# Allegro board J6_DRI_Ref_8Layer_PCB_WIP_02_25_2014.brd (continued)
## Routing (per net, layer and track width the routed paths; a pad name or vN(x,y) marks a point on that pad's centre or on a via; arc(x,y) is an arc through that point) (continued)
H_DDR1_D29: length 36.6
  TOP w0.102: U52.AA26 v1(61.35,49.34)
  TOP w0.127: v1(42.18,31.3) U66.C2
  BOTTOM w0.127: v1(42.18,31.3) 41.78,31.7 41.78,32.39 41.99,32.59 41.99,32.8 42.09,32.9 42.32,32.9 42.42,33 42.42,33.21 42.32,33.31 42.09,33.31 41.99,33.41 41.99,33.7 41.88,33.81 41.37,33.81 41.25,33.93 41.25,34.09 41.37,34.21 41.88,34.21 41.99,34.31 41.99,34.67 42.09,34.77 42.3,34.77 42.42,34.89 42.42,35.06 42.3,35.18 42.09,35.18 41.99,35.28 41.99,35.64 42.89,36.54 43.03,36.54 43.2,36.37 43.35,36.37 43.49,36.51 43.49,36.65 43.32,36.83 43.32,36.97 43.46,37.11 43.61,37.11 43.78,36.94 43.92,36.94 44.07,37.09 44.07,37.23 43.89,37.4 43.89,37.55 44.04,37.69 44.18,37.69 44.36,37.52 44.5,37.52 44.64,37.66 44.64,37.8 44.47,37.98 44.47,38.12 45.42,39.07 46.56,39.07 46.69,38.94 46.69,38.69 46.81,38.56 47.14,38.56 47.27,38.69 47.27,38.94 47.4,39.07 48.18,39.07 48.31,39.19 48.31,39.42 48.44,39.55 49.91,39.55 51.41,41.05 51.41,41.28 51.81,41.68 51.86,41.68 53.29,43.11 53.29,43.45 53.58,43.73 54.09,43.73 55.45,45.09 55.8,45.09 55.96,44.94 56.79,44.94 58.09,46.23 58.37,46.23 60.95,48.81 v1(61.35,49.34)
H_DDR1_D30: length 30.6
  TOP w0.102: U52.AA25 61.79,50.31 v1(61.38,49.95)
  TOP w0.127: v1(42.98,32.9) U66.A2
  BOTTOM w0.102: v1(61.38,49.95) 61.74,49.59 61.74,49.09 61.6,48.96 61.6,48.75
  BOTTOM w0.127: 61.6,48.75 59.01,46.15 58.91,46.15 58.17,45.42 57.79,45.42 57.51,45.13 57.51,44.55 56.31,43.36 55.8,43.36 51.51,39.07 50.79,39.07 50.05,38.33 48.39,38.33 47.92,37.86 46.11,37.86 45.41,37.16 44.91,37.16 43.56,35.81 43.17,35.81 42.98,35.63 42.98,34.19 42.88,34.09 42.61,34.09 42.49,33.97 42.49,33.8 42.61,33.68 42.88,33.68 42.98,33.58 v1(42.98,32.9)
H_DDR1_D31: length 32
  TOP w0.127: U52.AA28 61.93,47.28 61.06,46.41 61.06,43.46 60.68,43.08 60.68,40.24 59,38.56 57.84,38.56 57.37,38.09 57.37,37.71 56.63,36.97 55.9,36.97 55.45,36.52 55.45,35.49 55.19,35.23 46.59,35.23 45.75,34.39 45.75,31.5 45.85,31.4 46.08,31.4 46.18,31.3 46.18,31.1 46.08,30.99 45.85,30.99 45.75,30.89 45.75,30.48 46.13,30.09 U66.D7
H_DDR1_DQM0: length 43.4
  TOP w0.102: v1(59.13,51.63) U52.AD23
  TOP w0.127: U65.E7 v1(34.28,29.7)
  L3-SIGNAL w0.102: 58.75,48.9 58.75,49.39
  L3-SIGNAL w0.114: 58.75,49.39 58.75,49.66 59.54,50.45 59.54,51.22 v1(59.13,51.63) ; 58.75,48.9 58.57,48.72 57.99,48.72 56.9,47.63 54.89,47.63 54.66,47.86 53.92,47.86 52.73,46.66 52.73,44.07 50.5,41.84 49.91,41.84 49.4,41.33 48.26,41.33 47.74,40.81 47.54,40.81 46.81,40.08 46.81,39.88 45.42,38.48 44.96,38.48 44.53,38.05 39.95,38.05 38.18,36.28 38.18,36.13 38.61,35.7 38.61,35.54 38.49,35.42 38.32,35.42 37.89,35.85 37.75,35.85 37.59,35.68 37.59,35.54 38,35.12 38,34.96 37.88,34.84 37.71,34.84 37.3,35.25 37.16,35.25 36.86,34.95 36.86,31.52 36.27,30.94 35.53,30.94 v1(34.28,29.7)
H_DDR1_DQM1: length 48.1
  TOP w0.102: U65.D3 31.18,30.09 v1(31.52,30.43) ; 61.13,52.05 v1(61.57,51.65)
  BOTTOM w0.127: v1(31.52,30.43) 32.59,31.5 32.59,33.58 32.87,33.86 33.11,33.86 33.21,33.96 33.21,34.12 33.33,34.24 33.5,34.24 33.62,34.12 33.62,33.96 33.72,33.86 33.93,33.86 34.03,33.96 34.03,34.12 34.15,34.24 34.31,34.24 34.43,34.12 34.43,33.96 34.54,33.86 34.74,33.86 34.84,33.96 34.84,34.12 34.96,34.24 35.13,34.24 35.25,34.12 35.25,33.96 35.35,33.86 35.55,33.86 35.65,33.96 35.65,34.27 35.75,34.37 35.96,34.37 36.06,34.27 36.06,33.96 36.16,33.86 36.36,33.86 36.47,33.96 36.47,34.27 36.57,34.37 36.77,34.37 36.87,34.27 36.87,33.96 36.97,33.86 37.18,33.86 37.28,33.96 37.28,34.27 37.38,34.37 37.58,34.37 37.68,34.27 37.68,33.96 37.79,33.86 37.99,33.86 38.09,33.96 38.09,34.27 38.19,34.37 38.4,34.37 38.5,34.27 38.5,33.96 38.6,33.86 38.84,33.86 46.69,41.71 46.69,42.17 48.79,44.27 50.39,44.27 50.72,44.6 50.72,45.06 52.86,47.2 53.06,47.2 53.64,47.78 54.88,47.78 55.31,47.35 57.1,47.35 57.68,47.93 58.98,47.93 59.94,48.9 59.94,49.71 60.3,50.07 60.3,50.95 60.58,51.23 61.15,51.23 v1(61.57,51.65)
H_DDR1_DQM2: length 38.3
  TOP w0.102: v1(49.05,28.91) 49.03,28.89 ; v1(60.79,49.26) U52.AC26
  TOP w0.127: U66.E7 46.98,28.89 49.03,28.89
  L3-SIGNAL w0.114: v1(49.05,28.91) 49.05,29.51 49.15,29.62 49.38,29.62 49.48,29.72 49.48,29.92 49.38,30.02 49.15,30.02 49.05,30.12 49.05,30.33 49.15,30.43 49.38,30.43 49.48,30.53 49.48,30.73 49.38,30.83 49.15,30.83 49.05,30.94 49.05,31.14 49.15,31.24 49.38,31.24 49.48,31.34 49.48,31.55 49.38,31.65 49.15,31.65 49.05,31.75 49.05,31.95 49.15,32.05 49.38,32.05 49.48,32.16 49.48,32.36 49.38,32.46 49.15,32.46 49.05,32.56 49.05,32.76 49.15,32.87 49.38,32.87 49.48,32.97 49.48,33.17 49.38,33.27 49.15,33.27 49.05,33.37 49.05,33.58 49.15,33.68 49.38,33.68 49.48,33.78 49.48,33.98 49.38,34.09 49.15,34.09 49.05,34.19 49.05,34.39 49.15,34.49 49.38,34.49 49.48,34.59 49.48,34.8 49.38,34.9 49.15,34.9 49.05,35 49.05,35.64 49.44,36.03 49.58,36.03 49.78,35.83 49.92,35.83 50.07,35.97 50.07,36.11 49.87,36.31 49.87,36.46 50.01,36.6 50.15,36.6 50.35,36.4 50.5,36.4 50.64,36.55 50.64,36.69 50.44,36.89 50.44,37.03 50.59,37.18 50.73,37.18 50.93,36.98 51.07,36.98 51.22,37.12 51.22,37.27 51.02,37.46 51.02,37.61 51.16,37.75 51.3,37.75 51.5,37.55 51.65,37.55 51.79,37.7 51.79,37.84 51.59,38.04 51.59,38.18 51.74,38.33 51.88,38.33 52.08,38.13 52.22,38.13 52.37,38.27 52.37,38.42 52.17,38.61 52.17,38.76 52.31,38.9 52.45,38.9 52.65,38.7 52.8,38.7 52.94,38.85 52.94,38.99 52.74,39.19 52.74,39.33 52.89,39.48 53.03,39.48 53.23,39.28 53.37,39.28 53.52,39.42 53.52,39.57 53.32,39.76 53.32,39.91 56.54,43.13 57.12,43.13 57.38,43.39 57.38,43.97 58.7,45.29 58.7,46.31 60.73,48.34 60.73,48.59 60.79,48.65 v1(60.79,49.26)
H_DDR1_DQM3: length 43.3
  TOP w0.127: U52.AA27 61.49,48.41 61.49,47.25 60.78,46.54 60.78,43.64 60.33,43.18 60.33,40.62 59.79,40.08 58.27,40.08 56.05,37.86 55.49,37.86 54.94,37.32 54.94,35.94 54.83,35.82 54.64,35.82 54.51,35.94 54.51,36.35 54.38,36.48 54.21,36.48 54.08,36.35 54.08,35.63 53.96,35.51 53.79,35.51 53.67,35.63 53.67,35.77 53.55,35.89 53.37,35.89 53.24,35.77 53.24,35.61 53.14,35.51 52.94,35.51 52.84,35.61 52.84,35.77 52.72,35.89 52.55,35.89 52.43,35.77 52.43,35.61 52.33,35.51 52.13,35.51 52.02,35.61 52.02,35.77 51.9,35.89 51.74,35.89 51.62,35.77 51.62,35.61 51.52,35.51 51.31,35.51 51.21,35.61 51.21,35.92 51.11,36.02 47.42,36.02 47.17,36.27 v2(46.76,36.27) ; v1(43.78,30.49) U66.D3
  BOTTOM w0.127: v2(46.76,36.27) 45.92,36.27 45.8,36.15 45.8,35.89 45.92,35.77 46.37,35.77 46.46,35.68 46.46,34.83 46.23,34.59 46.08,34.59 45.44,35.24 45.27,35.24 45.15,35.12 45.15,34.95 45.79,34.31 45.79,34.16 45.65,34.02 45.51,34.02 44.8,34.73 44.63,34.73 44.51,34.61 44.51,34.44 45.22,33.73 45.22,33.59 45.08,33.44 44.93,33.44 44.57,33.81 44.43,33.81 44.28,33.66 44.28,33.52 44.64,33.16 44.64,33.01 43.21,31.57 43.21,31.07 v1(43.78,30.49)
H_DDR1_DQM_ECC: length 29.4
  TOP w0.102: v1(63.75,49.34) U52.V26
  TOP w0.127: v1(59.05,30.27) U67.B7
  L3-SIGNAL w0.102: 62.56,47.17 62.18,46.79
  L3-SIGNAL w0.114: 62.56,47.17 62.56,47.35 63.75,48.54 v1(63.75,49.34) ; 62.18,46.79 61.8,46.41 61.8,40.85 60.91,39.96 60.91,39.61 60.81,39.5 60.3,39.5 60.2,39.4 60.2,39.2 60.3,39.1 60.81,39.1 60.91,39 60.91,38.79 60.81,38.69 60.3,38.69 60.2,38.59 60.2,38.39 60.3,38.28 60.81,38.28 60.91,38.18 60.91,37.98 60.81,37.88 60.3,37.88 60.2,37.78 60.2,37.57 60.3,37.47 60.81,37.47 60.91,37.37 60.91,37.17 60.81,37.07 60.3,37.07 60.2,36.96 60.2,36.76 60.3,36.66 60.83,36.66 60.91,36.58 60.91,36.35 60.81,36.25 60.3,36.25 60.2,36.15 60.2,35.95 60.3,35.85 60.81,35.85 60.91,35.74 60.91,35.51 60.78,35.38 60.4,35.38 60.31,35.3 60.31,33.28 60.44,33.15 60.66,33.15 60.78,33.02 60.78,32.64 60.66,32.51 59.86,32.51 59.05,31.7 v1(59.05,30.27)
H_DDR1_DQS0: length 41.8
  TOP w0.089: 53.8,50.06 53.78,50.06 53.77,50.05 50.87,50.05 49.96,49.14 49.96,48.59 49.38,48.01 48.84,48.01 47.84,47.01 47.84,46.45 48.41,45.88 48.41,45.59 47.75,44.94 47.07,44.94 46.81,44.68 46.81,42.98 41.9,38.07 40.46,38.07 38.67,36.28 34.68,36.28 32.12,33.72 32.12,31.06 32.45,30.73 32.45,30.19 32.02,29.75 32.02,28.98 31.85,28.82 31.73,28.82 31.58,28.97 31.45,28.97 31.33,28.84 31.33,28.71 31.47,28.57 31.47,28.44 31.09,28.06 30.81,28.06 30.68,28.18 U65.F3
  TOP w0.102: U52.AH25 56.2,50.32 55.41,50.32 55.15,50.06 53.8,50.06
H_DDR1_DQS1: length 54.5
  TOP w0.089: U52.AE27 58.73,48.6 58.35,48.17 58.35,47.86 58.39,47.82 ; U65.C7 33.81,30.97 33.38,30.97 32.96,31.38 32.96,33.21 34.35,34.6 35.77,34.6 36.01,34.36 36.01,33.05 36.14,32.92 36.51,32.92 36.64,33.05 36.64,34.36 36.88,34.6 37.48,34.6 37.72,34.36 37.72,29.8 37.85,29.67 38.22,29.67 38.35,29.8 38.35,34.36 38.59,34.6 40.16,34.6 40.35,34.79 40.35,35.31 39.97,35.69 39.97,36.09 40.66,36.78 41.07,36.78 41.41,36.43 41.56,36.43 47.3,42.17 47.88,42.17 48.07,42.35 48.07,42.59 47.86,42.79 47.86,43.55 47.86,43.9 48.56,44.59 49.08,44.59 49.28,44.39 49.72,44.39 49.92,44.59 50.68,44.59 51.13,44.15 52.31,44.15 52.46,43.99 52.64,43.81 52.64,43.27 52.8,43.11 53.05,43.11 53.75,43.81 54,43.81 54.3,44.11 55.51,44.11 55.96,43.67 56.95,43.67 58.31,45.02 58.31,46.67 58.3,46.68 58.3,46.77 58.29,46.77 58.29,46.79
  TOP w0.102: 58.39,47.82 58.45,47.76 58.45,47.55 58.29,47.39 58.29,46.79
H_DDR1_DQS2: length 44.4
  TOP w0.089: U52.AD27 59.53,48.59 59.13,48.08 59.13,47.88 59.19,47.82 ; U66.F3 44.19,28.49 44.35,28.65 44.35,31.5 44.02,31.83 44.02,32.39 44.35,32.72 44.35,33.46 44.2,33.61 41.63,33.61 41.31,33.93 41.31,35.01 42.2,35.9 42.28,35.98 42.75,35.98 43.19,35.54 43.34,35.54 43.63,35.83 43.63,35.98 43.13,36.49 43.13,36.82 43.56,37.25 43.9,37.25 44.4,36.75 44.55,36.75 44.84,37.04 44.84,37.19 44.34,37.7 44.34,37.81 44.34,37.81 44.34,38.03 45.85,39.55 48.33,39.55 48.77,39.98 49.53,39.98 49.79,39.73 50.3,39.73 50.7,40.13 50.7,40.57 50.97,40.83 51.15,40.83 51.49,41.17 51.49,41.88 51.81,42.2 52.33,42.2 52.63,41.91 52.63,41.6 52.63,40.16 52.76,40.03 53.19,40.03 53.31,40.16 53.31,41.54 53.61,41.83 55.37,41.83 56.67,43.13 57.38,43.13 58.99,44.74 58.99,46.67 58.99,46.68 58.99,46.77 58.98,46.77 58.98,46.79
  TOP w0.102: 59.19,47.82 59.25,47.76 59.25,47.55 58.98,47.28 58.98,46.79
H_DDR1_DQS3: length 48.4
  TOP w0.089: U66.C7 47.02,31.33 47.02,33.46 46.62,33.85 46.62,34.1 46.85,34.33 48.07,34.33 48.18,34.23 48.18,33.7 48.44,33.44 49.08,33.44 49.34,33.7 49.34,34.1 49.45,34.21 49.79,34.21 49.89,34.1 49.89,32.61 50.18,32.32 50.77,32.32 51.05,32.61 51.05,34.1 51.16,34.21 51.5,34.21 51.6,34.1 51.6,31.21 51.89,30.93 52.48,30.93 52.76,31.21 ; 52.76,31.57 52.76,34.1 52.87,34.21 53.27,34.21 53.38,34.1 53.38,32.47 53.66,32.18 54.26,32.18 54.54,32.47 54.54,34.04 54.7,34.21 55.59,34.21 56.05,34.66 56.53,34.66 57.5,35.64 57.5,36.2 57.63,36.32 58.09,36.32 58.73,35.69 59.42,35.69 59.69,35.96 59.69,36.4 59.4,36.69 59.4,37.38 59.5,37.49 59.74,37.49 59.87,37.36 59.87,37.15 60.15,36.87 60.7,36.87 60.99,37.15 60.99,37.71 60.41,38.28 60.41,38.76 61.99,40.33 61.99,43.5 61.81,43.67 61.81,46.25 62.08,46.52 62.08,46.52 62.34,46.78 62.35,46.78 62.36,46.79 ; 62.62,47.69 62.73,47.8 U52.Y28
  TOP w0.102: 62.36,46.79 62.62,47.05 62.62,47.69 ; 52.76,31.57 52.76,31.21
H_DDR1_DQS_ECC: length 38.3
  TOP w0.089: U67.C3 56.37,29.06 56.46,29.16 56.46,30.19 56.7,30.43 57.53,30.43 57.63,30.54 57.63,30.95 57.53,31.06 56,31.06 55.71,31.34 ; U52.V27 64.33,48.62 63.94,48.13 ; 55.71,31.57 55.71,31.86 56,32.15 57.53,32.15 57.63,32.25 57.63,32.67 57.53,32.77 56.7,32.77 56.46,33.01 56.46,33.63 57.33,34.5 58.61,34.5 59.11,34 59.11,32.62 59.29,32.44 60.96,32.44 61.76,33.24 61.76,33.52 61.21,34.08 60.84,34.08 60.15,34.77 60.15,35.77 60.54,36.16 62.26,36.16 62.73,36.62 62.73,38.09 63.21,38.57 63.9,38.57 64.15,38.83 64.15,46.42 63.93,46.64 63.93,46.79
  TOP w0.102: 55.71,31.34 55.71,31.57 ; 63.94,48.13 63.94,47.66 63.93,47.66 63.93,46.79
H_DDR1_DQSN0: length 41.8
  TOP w0.089: 53.8,49.78 53.78,49.78 53.77,49.79 50.99,49.79 50.23,49.03 50.23,48.48 49.49,47.74 48.95,47.74 48.11,46.9 48.11,46.56 48.67,45.99 48.67,45.48 47.86,44.67 47.18,44.67 47.08,44.57 47.08,42.87 42.01,37.8 40.57,37.8 38.78,36.02 34.79,36.02 32.39,33.61 32.39,31.17 32.72,30.84 32.72,30.08 32.28,29.64 32.28,28.87 31.2,27.79 30.78,27.79 U65.G3 ; U52.AG25 56.8,50.45
  TOP w0.102: 56.8,50.45 56.66,50.32 56.66,50.32 56.39,50.04 55.53,50.04 55.27,49.78 53.8,49.78
H_DDR1_DQSN1: length 54.4
  TOP w0.089: 58.57,46.79 58.57,44.91 57.06,43.4 55.85,43.4 55.4,43.84 54.41,43.84 54.11,43.54 53.86,43.54 53.16,42.84 52.69,42.84 52.37,43.16 52.37,43.7 52.2,43.88 51.02,43.88 50.57,44.33 50.03,44.33 49.83,44.13 49.17,44.13 48.97,44.33 48.67,44.33 48.13,43.79 48.13,42.9 48.34,42.7 48.34,42.44 48.34,42.44 48.34,42.24 47.99,41.9 47.77,41.9 47.77,41.9 47.41,41.9 41.67,36.16 41.45,36.16 41.45,36.16 41.3,36.16 40.95,36.51 40.78,36.51 40.24,35.98 40.24,35.8 40.62,35.42 40.62,34.68 40.27,34.33 38.7,34.33 38.62,34.25 38.62,29.69 38.33,29.4 37.74,29.4 37.46,29.69 37.46,34.25 37.37,34.33 36.99,34.33 36.9,34.25 36.9,32.94 36.62,32.65 36.03,32.65 35.75,32.94 35.75,34.25 35.66,34.33 34.46,34.33 34.2,34.07 34.2,33.95 34.48,33.66 34.48,33.52 34.37,33.41 34.23,33.41 33.94,33.69 33.82,33.69 33.23,33.1 33.23,31.49 33.49,31.23 33.77,31.23 33.88,31.35 U65.B7
  TOP w0.102: 58.57,46.79 58.57,47.27 58.73,47.43 U52.AE28
H_DDR1_DQSN2: length 44.3
  TOP w0.089: U66.G3 43.38,28.04 43.57,28.23 44.3,28.23 44.61,28.54 44.61,31.61 44.28,31.94 44.28,32.28 44.46,32.45 44.61,32.61 44.61,33.57 44.31,33.87 41.74,33.87 41.57,34.04 41.57,34.9 42.2,35.53 42.39,35.71 42.64,35.71 43.08,35.27 43.45,35.27 43.9,35.72 43.9,36.09 43.39,36.6 43.39,36.71 43.67,36.99 43.78,36.99 44.29,36.48 44.66,36.48 45.11,36.93 45.11,37.3 44.6,37.81 44.6,37.81 44.6,37.92 45.96,39.28 48.44,39.28 48.88,39.72 49.42,39.72 49.68,39.46 50.41,39.46 50.97,40.02 50.97,40.46 51.08,40.57 51.26,40.57 51.75,41.06 51.75,41.77 51.92,41.94 52.22,41.94 52.36,41.8 52.36,40.05 52.52,39.89 52.65,39.77 53.3,39.77 53.58,40.05 53.58,41.43 53.71,41.56 55.47,41.56 56.78,42.87 57.49,42.87 59.26,44.63 59.26,46.79
  TOP w0.102: U52.AD28 59.53,47.44 59.26,47.16 59.26,46.79
H_DDR1_DQSN3: length 48.4
  TOP w0.089: 62.35,48.16 62.73,48.53 U52.Y27 ; 52.6,34.32 52.65,34.37 52.76,34.47 53.38,34.47 53.65,34.21 53.65,32.58 53.77,32.45 54.15,32.45 54.27,32.58 54.27,34.15 54.59,34.47 55.48,34.47 55.93,34.93 56.42,34.93 57.24,35.75 57.24,36.31 57.52,36.59 58.2,36.59 58.84,35.96 59.3,35.96 59.42,36.07 59.42,36.29 59.13,36.58 59.13,37.49 59.39,37.75 59.85,37.75 60.13,37.47 60.13,37.26 60.26,37.14 60.59,37.14 60.72,37.26 60.72,37.6 60.15,38.17 60.15,38.87 61.72,40.44 61.72,43.39 61.54,43.56 61.54,46.36 61.92,46.73 62.09,46.9 62.15,46.97 62.15,46.98 62.16,46.99 ; 62.35,47.81 62.35,47.8 62.35,47.71 62.34,47.71 62.34,47.69 ; U66.B7 46.18,32.09 46.18,33.46 46.36,33.63 46.36,34.21 46.74,34.6 48.19,34.6 48.45,34.34 48.45,33.81 48.55,33.71 48.97,33.71 49.07,33.81 49.07,34.21 49.33,34.47 49.9,34.47 50.16,34.21 50.16,32.72 50.29,32.59 50.66,32.59 50.78,32.72 50.78,34.21 51.05,34.47 51.61,34.47 51.72,34.37 51.87,34.21 51.87,31.32 52,31.19 52.37,31.19 52.5,31.32 52.5,34.21
  TOP w0.102: 62.34,47.69 62.34,47.16 62.16,46.99 ; 62.35,48.16 62.35,47.81 ; 52.6,34.32 52.5,34.21
H_DDR1_DQSN_ECC: length 38.3
  TOP w0.089: U52.V28 64.33,47.79 64.2,47.66 ; 64.21,46.79 64.21,46.77 64.2,46.75 64.42,46.53 64.42,38.72 64.01,38.31 63.32,38.31 62.99,37.98 62.99,36.51 62.37,35.89 60.65,35.89 60.41,35.66 60.41,34.88 60.95,34.34 61.32,34.34 62.03,33.63 62.03,33.13 61.07,32.17 59.18,32.17 58.84,32.51 58.84,33.89 58.5,34.23 57.44,34.23 56.73,33.52 56.73,33.12 56.81,33.04 57.64,33.04 57.9,32.78 57.9,32.14 57.64,31.88 56.11,31.88 55.98,31.75 55.98,31.57 ; 55.98,31.45 56.11,31.32 57.64,31.32 57.9,31.06 57.9,30.43 57.64,30.17 56.81,30.17 56.73,30.08 56.73,29.05 56.48,28.79 55.64,28.79 55.45,28.61 U67.D3
  TOP w0.102: 64.21,46.79 64.21,47.66 64.2,47.66 ; 55.98,31.45 55.98,31.57
H_DDR1_ECC_D0: length 29.7
  TOP w0.102: v1(63.94,53.25) U52.W22
  TOP w0.127: v1(59.05,27.87) U67.E8
  L3-SIGNAL w0.102: 64.21,46.79 64.21,47.95 ; 64.31,51.72 64.31,52.89
  L3-SIGNAL w0.114: 64.21,47.95 64.6,48.34 64.6,51.42 64.31,51.72 ; 64.21,46.79 64.21,46.46 63.76,46.01 63.76,40.85 62.59,39.68 62.59,33.05 61.11,31.57 60.45,31.57 60.25,31.37 60.25,29.27 60.04,29.06 59.66,29.06 59.46,28.86 59.46,28.28 v1(59.05,27.87) ; 64.31,52.89 v1(63.94,53.25)
H_DDR1_ECC_D1: length 27.5
  TOP w0.102: v1(63.93,52.41) U52.V23
  TOP w0.127: v1(59.85,29.47) U67.C8
  L3-SIGNAL w0.102: 63.53,51.46 63.53,52.01
  L3-SIGNAL w0.114: v1(59.85,29.47) 59.45,29.87 59.45,31.38 60.05,31.98 60.99,31.98 62.2,33.2 62.2,41.46 63.14,42.39 63.14,47.48 63.37,47.71 63.46,47.71 64.27,48.52 64.27,51.06 64.07,51.26 63.73,51.26 63.53,51.46 ; 63.53,52.01 v1(63.93,52.41)
H_DDR1_ECC_D2: length 33.6
  TOP w0.102: U52.W19 v1(63.93,54.85)
  TOP w0.127: v1(55.05,27.87) U67.E3
  BOTTOM w0.102: 63.6,54.52 63.55,54.47 63.55,53.09 63.8,52.83 ; 64.34,48.19 64.58,48.43 64.58,51.53
  BOTTOM w0.127: 63.8,52.83 64.08,52.83 64.34,52.58 64.34,52.29 64.34,52.29 64.34,51.77 64.58,51.53 ; 64.34,48.19 64.34,46.12 62.85,44.63 61.82,44.63 60.73,43.54 60.73,40.44 60.96,40.21 60.96,33.78 v1(55.05,27.87) ; 63.6,54.52 v1(63.93,54.85)
H_DDR1_ECC_D3: length 33.6
  TOP w0.102: U52.W23 v1(63.91,51.65)
  TOP w0.127: v1(55.05,28.67) U67.D2
  BOTTOM w0.102: v1(63.91,51.65) 64.29,51.27 64.29,49.96 64.36,49.89 64.36,48.8 64.01,48.44
  BOTTOM w0.127: v1(55.05,28.67) 58.55,32.17 58.55,32.32 58.31,32.56 58.31,32.7 58.45,32.85 58.59,32.85 58.84,32.6 58.98,32.6 59.13,32.75 59.13,32.89 58.88,33.14 58.88,33.28 59.02,33.42 59.17,33.42 59.41,33.18 59.56,33.18 59.7,33.32 59.7,33.47 59.18,33.99 59.18,34.16 59.3,34.28 59.46,34.28 59.99,33.75 60.13,33.75 60.28,33.9 60.28,34.04 59.75,34.57 59.75,34.73 59.87,34.85 60.04,34.85 60.45,34.44 60.71,34.7 60.71,38.34 60.48,38.57 60.48,44.27 61.87,45.67 62.76,45.67 64.01,46.92 64.01,48.44
H_DDR1_ECC_D4: length 29.4
  TOP w0.102: v1(63.23,49.82) U52.Y25
  TOP w0.127: v1(59.05,29.47) U67.C7
  L3-SIGNAL w0.102: 62.18,47.32 61.65,46.79
  L3-SIGNAL w0.114: 62.18,47.32 62.18,47.53 63,48.35 63,48.78 62.78,49.01 62.78,49.61 62.9,49.74 v1(63.23,49.82) ; v1(59.05,29.47) 58.58,29.93 58.58,30.87 58.48,30.98 58.06,30.98 57.94,31.09 57.94,31.26 58.06,31.38 58.48,31.38 58.58,31.48 58.58,31.69 58.48,31.79 57.73,31.79 57.61,31.91 57.61,32.08 57.73,32.19 58.73,32.19 59.15,32.61 59.15,32.75 58.72,33.18 58.72,33.33 58.87,33.47 59.01,33.47 59.44,33.04 59.58,33.04 59.77,33.23 59.77,39.58 60.4,40.21 60.6,40.21 60.91,40.52 60.91,40.69 60.68,40.92 60.27,40.92 60.15,41.04 60.15,41.21 60.73,41.79 60.73,45.87 61.65,46.79
H_DDR1_ECC_D5: length 30.9
  TOP w0.102: v1(63.88,50.85) U52.V24
  TOP w0.127: v1(58.25,27.87) U67.E7
  L3-SIGNAL w0.114: v1(58.25,27.87) 58.57,28.19 58.57,29.11 58.1,29.58 58.1,30.2 57.97,30.33 57.2,30.33 57.07,30.46 57.07,32.88 57.2,33 57.78,33 58.08,32.7 58.23,32.7 58.37,32.85 58.37,32.99 58.07,33.29 58.07,33.44 59.26,34.62 59.26,39.01 58.95,39.01 58.69,39.27 58.69,39.81 58.95,40.06 59.31,40.06 59.47,39.91 59.64,40.08 59.64,43.39 60.3,44.05 60.3,45.87 61.8,47.37 61.8,47.68 62.38,48.26 62.38,49.61 63.07,50.29 63.58,50.29 63.88,50.59 v1(63.88,50.85)
H_DDR1_ECC_D6: length 32.4
  TOP w0.102: v1(63.78,49.95) U52.V25
  TOP w0.127: v1(55.05,29.47) U67.C2
  BOTTOM w0.102: 62.36,46.79 63.6,48.03 ; v1(63.78,49.95) 64.13,49.6 64.13,49.15
  BOTTOM w0.127: 64.13,49.15 63.6,48.62 63.6,48.03 ; v1(55.05,29.47) 55.78,30.2 55.78,30.46 55.95,30.63 56.21,30.63 56.41,30.83 56.41,31.09 55.85,31.66 55.85,31.82 55.97,31.94 56.14,31.94 56.77,31.31 56.94,31.31 57.06,31.43 57.06,31.6 56.46,32.19 56.46,32.33 56.61,32.48 56.75,32.48 57.28,31.95 57.45,31.95 57.57,32.07 57.57,32.24 57.04,32.77 57.04,32.91 57.18,33.05 57.33,33.05 57.55,32.83 57.69,32.83 57.84,32.97 57.84,33.12 57.61,33.34 57.61,33.48 57.76,33.63 57.9,33.63 58.13,33.4 58.27,33.4 58.41,33.55 58.41,33.69 58.19,33.92 58.19,34.06 59.76,35.63 59.9,35.63 60.12,35.4 60.29,35.4 60.41,35.52 60.41,35.69 60.19,35.92 60.19,36.06 60.22,36.1 60.22,44.66 62.36,46.79
H_DDR1_ECC_D7: length 31.8
  TOP w0.102: v1(63.19,49.26) U52.Y26
  TOP w0.127: v1(55.05,30.27) U67.B3
  BOTTOM w0.127: v1(55.05,30.27) 55.05,32.7 55.5,33.15 56.04,33.15 56.26,32.93 56.4,32.93 56.55,33.08 56.55,33.22 56.18,33.59 56.18,33.76 56.3,33.87 56.47,33.87 56.83,33.51 56.98,33.51 57.12,33.65 57.12,33.8 56.76,34.16 56.76,34.33 56.88,34.45 57.04,34.45 57.41,34.09 57.55,34.09 57.7,34.23 57.7,34.37 57.33,34.74 57.33,34.91 57.45,35.03 57.62,35.03 57.98,34.66 58.13,34.66 58.27,34.8 58.27,34.95 57.91,35.31 57.91,35.48 58.03,35.6 58.19,35.6 58.56,35.24 58.7,35.24 58.85,35.38 58.85,35.52 58.48,35.89 58.48,36.06 58.6,36.18 59.21,36.18 59.42,36.39 59.42,36.87 59.97,37.41 59.97,37.64 59.87,37.75 59.5,37.75 59.39,37.86 59.39,38.03 59.5,38.15 59.87,38.15 59.97,38.25 59.97,38.46 59.87,38.56 59.5,38.56 59.39,38.68 59.39,38.85 59.5,38.96 59.87,38.96 59.97,39.07 59.97,39.27 59.87,39.37 59.87,39.78 59.97,39.88 59.97,44.81 63.19,48.03 v1(63.19,49.26)
H_DDR1_ODT0: length 124.7
  TOP w0.102: U52.AE20 58.59,54.59 v1(58.23,55.01)
  TOP w0.127: U67.G1 53.45,26.25 TP2MC1.1 ; TP1MB5.1 U66.K1 ; RN2.1 v1(62.39,27.57) ; TP1MA5.1 U65.K1
  L3-SIGNAL w0.102: 49.86,25.5 50.61,26.25 52.69,26.25
  L3-SIGNAL w0.114: v2(23.75,33.15) 24.84,34.24 26.24,34.24 26.37,34.11 26.37,33.59 26.24,33.47 24.94,33.47 24.84,33.36 24.84,33.16 24.94,33.06 26.25,33.06 26.37,32.94 26.37,32.77 26.25,32.65 24.94,32.65 24.84,32.55 24.84,32.35 24.94,32.25 26.25,32.25 26.37,32.13 26.37,31.96 26.25,31.84 24.94,31.84 24.84,31.74 24.84,31.54 24.94,31.43 26.25,31.43 26.37,31.31 26.37,31.15 26.25,31.03 24.94,31.03 24.84,30.93 24.84,30.72 24.94,30.62 26.25,30.62 26.37,30.5 26.37,30.33 26.25,30.21 24.94,30.21 24.84,30.11 24.84,29.91 24.94,29.81 26.25,29.81 26.37,29.69 26.37,29.52 26.25,29.4 24.94,29.4 24.84,29.3 24.84,29.1 24.94,29 26.15,29 26.37,28.78 26.37,27.26 27.93,25.69 TP1MA5.1 ; 49.86,25.5 49.66,25.3 49.23,25.3 49.05,25.48 48.23,25.48 48.06,25.3 46,25.3 45.69,25.61 45.69,25.86 45.36,26.19 41.88,26.19 TP1MB5.1 ; v1(62.39,27.57) 62.38,27.56 61.8,27.56 60.4,26.16 59.82,26.16 59.41,25.76 58.01,25.76 57.89,25.89 54.99,25.89 54.74,26.14 53.8,26.14 53.68,26.25 TP2MC1.1 52.69,26.25
  BOTTOM w0.127: TP1MA5.1 28.86,25.52 28.86,25.44 29.23,25.07 29.55,25.07 30.12,24.5 30.45,24.5 30.64,24.69 31.57,24.69 32.79,23.47 34.44,23.47 34.8,23.83 35.05,23.83 35.71,24.49 36.2,24.49 36.27,24.41 39.29,24.41 40.03,25.15 40.84,25.15 TP1MB5.1 ; v2(23.75,33.15) 23.75,32.79 23.62,32.67 22.94,32.67 22.81,32.79 22.81,33.61 22.94,33.73 23.85,33.73 23.95,33.84 23.95,34.01 23.85,34.11 22.82,34.11 22.71,34.23 22.71,34.38 22.82,34.5 23.85,34.5 23.95,34.6 23.95,34.78 23.85,34.88 22.92,34.88 22.81,34.99 22.81,35.15 22.92,35.26 23.65,35.26 23.75,35.36 23.75,36.63 35.71,48.59 39.7,48.59 39.95,48.34 44.95,48.34 49.73,53.13 55.31,53.13 56.77,54.59 57.81,54.59 v1(58.23,55.01)
H_DDR1_RASN: length 123.4
  TOP w0.102: v1(57.61,55.04) U52.AF20
  TOP w0.127: TP1MC1.1 55.85,27.07 U67.F3 ; TP1MB6.1 U66.J3 ; U65.J3 TP1MA6.1
  L3-SIGNAL w0.114: v2(23.27,30.94) 22.66,30.94 22.53,31.07 22.53,31.7 22.66,31.83 23.95,31.83 24.07,31.95 24.07,32.09 23.95,32.21 23.06,32.21 22.94,32.33 22.94,32.47 23.06,32.59 24.33,32.59 24.46,32.46 24.46,31.39 24.36,31.29 23.94,31.29 23.83,31.17 23.83,31.01 23.94,30.89 24.36,30.89 24.46,30.78 24.46,30.58 24.36,30.48 22.8,30.48 22.68,30.36 22.68,30.19 22.8,30.07 24.36,30.07 24.46,29.97 24.46,29.77 24.36,29.67 24.05,29.67 23.95,29.57 23.95,29.36 24.05,29.26 24.36,29.26 24.46,29.16 24.46,28.4 24.97,27.89 25.22,27.89 25.35,28.02 25.35,28.4 25.48,28.53 25.73,28.53 25.86,28.4 25.86,25.96 25.98,25.83 26.37,25.83 26.64,26.11 26.87,26.11 27.51,25.48 27.51,25.22 27.64,25.1 27.93,25.1 28.13,25.3 30.69,25.3 TP1MA6.1 31.53,25.24 32.05,25.24 32.44,25.63 32.94,25.63 33.33,25.24 33.81,25.24 33.91,25.15 34.65,25.15 34.8,25.3 35.36,25.3 35.41,25.35 36.88,25.35 37.19,25.66 39.01,25.66 39.47,25.2 41.59,25.2 41.69,25.3 43.39,25.3 TP1MB6.1
  BOTTOM w0.127: RN13.4 63.57,27.57 63.09,28.04 62.28,28.04 60.91,26.67 57.04,26.67 TP1MC1.1 56.32,27.07 55.5,26.24 53.62,26.24 53.24,25.86 52.78,25.86 52.45,26.19 50.65,26.19 49.76,25.3 47.61,25.3 47.38,25.54 47.38,25.89 47.17,26.1 46.61,26.1 46.55,26.16 45.77,26.16 44.88,25.28 44.2,25.28 TP1MB6.1 ; v1(57.61,55.04) 55.76,55.04 55.75,55.03 51.88,55.03 50.47,53.62 49.78,53.62 44.88,48.72 40.34,48.72 40.08,48.97 35.59,48.97 23.42,36.81 23.42,36.53 22.16,35.27 22.16,35.12 22.34,34.94 22.34,34.79 22.2,34.65 22.06,34.65 21.87,34.83 21.73,34.83 21.29,34.39 21.29,34.17 21.39,34.06 21.8,34.06 21.92,33.94 21.92,33.78 21.8,33.66 21.58,33.66 21.46,33.54 21.46,33.37 21.58,33.25 21.8,33.25 21.92,33.13 21.92,32.96 21.8,32.84 21.39,32.84 21.29,32.74 21.29,32.31 20.9,31.93 20.9,31.5 21.03,31.37 21.34,31.37 21.46,31.5 21.46,31.7 21.59,31.83 22.11,31.83 22.24,31.96 22.24,32.27 22.36,32.39 22.52,32.39 22.64,32.27 22.64,31.68 22.74,31.57 22.95,31.57 23.05,31.68 23.05,31.91 23.17,32.03 23.34,32.03 23.46,31.91 23.46,31.68 23.56,31.57 23.83,31.57 23.95,31.45 23.95,31.07 23.83,30.94 v2(23.27,30.94)
H_DDR1_RST: length 94
  TOP w0.127: U65.T2 v2(29.88,18.68) 26.43,18.68 24.84,20.27 24.84,23.65 24.46,24.03 24.46,30.43 23.29,31.6 23.29,36.38 33.35,46.43 43.05,46.43 49.43,52.81 55.5,52.81 55.96,53.27 56.74,53.27 U52.AG21 ; U67.N2 54.25,20.66 v1(54.25,19.85) ; U66.T2 v2(42.58,18.68)
  L3-SIGNAL w0.114: v1(54.25,19.85) 53.01,18.61 45.65,18.61 45.38,18.88 43.64,18.88 43.44,18.68 v2(42.58,18.68) 39,18.68 38.38,18.06 30.5,18.06 v2(29.88,18.68)
H_DDR1_WEN: length 130.5
  TOP w0.102: U65.L3 TP1MA7.1
  TOP w0.127: U66.L3 TP1MB7.1 ; v2(23.9,27.26) 23.9,27.71 23.8,27.82 22.28,27.82 22.17,27.92 22.17,28.12 22.28,28.22 23.83,28.22 23.95,28.34 23.95,28.51 23.83,28.63 22.28,28.63 22.17,28.73 22.17,29.7 22.28,29.8 23.83,29.8 23.95,29.92 23.95,30.18 23.83,30.3 22.94,30.3 22.81,30.43 22.81,36.53 33.1,46.81 33.85,46.81 33.95,46.92 33.95,47.58 34.07,47.7 34.23,47.7 34.35,47.58 34.35,46.92 34.46,46.81 34.66,46.81 34.76,46.92 34.76,47.58 34.88,47.7 35.05,47.7 35.17,47.58 35.17,46.92 35.27,46.81 35.47,46.81 35.57,46.92 35.57,47.58 35.69,47.7 35.86,47.7 35.98,47.58 35.98,46.92 36.08,46.81 36.28,46.81 36.39,46.92 36.39,47.58 36.5,47.7 36.67,47.7 36.79,47.58 36.79,46.92 36.89,46.81 37.1,46.81 37.2,46.92 37.2,47.58 37.32,47.7 37.49,47.7 37.6,47.58 37.6,46.92 37.71,46.81 37.91,46.81 38.01,46.92 38.01,47.58 38.13,47.7 38.3,47.7 38.42,47.58 38.42,46.92 38.52,46.81 38.72,46.81 38.82,46.92 38.82,47.58 38.94,47.7 39.11,47.7 39.23,47.58 39.23,46.92 39.33,46.81 39.54,46.81 39.64,46.92 39.64,47.58 39.76,47.7 39.92,47.7 40.04,47.58 40.04,46.92 40.14,46.81 40.35,46.81 40.45,46.92 40.45,47.71 40.57,47.83 40.74,47.83 40.86,47.71 40.86,46.92 40.96,46.81 41.16,46.81 41.26,46.92 41.26,47.71 41.38,47.83 41.55,47.83 41.67,47.71 41.67,46.92 41.77,46.81 41.97,46.81 42.08,46.92 42.08,47.73 42.18,47.83 42.38,47.83 42.48,47.73 42.48,46.92 42.58,46.81 42.87,46.81 43.66,47.6 43.66,47.75 43.42,47.98 43.42,48.13 43.57,48.27 43.71,48.27 43.95,48.03 44.09,48.03 44.24,48.18 44.24,48.32 44,48.56 44,48.7 44.14,48.85 44.29,48.85 44.52,48.61 44.67,48.61 44.81,48.75 44.81,48.9 44.57,49.13 44.57,49.28 44.72,49.42 44.86,49.42 45.1,49.18 45.24,49.18 45.39,49.33 45.39,49.47 45.15,49.71 45.15,49.85 45.29,50 45.44,50 45.67,49.76 45.82,49.76 45.96,49.9 45.96,50.05 45.72,50.28 45.72,50.43 45.87,50.57 46.01,50.57 46.25,50.33 46.39,50.33 46.54,50.48 46.54,50.62 46.3,50.86 46.3,51 46.44,51.15 46.59,51.15 46.82,50.91 46.97,50.91 47.11,51.05 47.11,51.2 46.87,51.43 46.87,51.58 47.02,51.72 47.16,51.72 47.4,51.48 47.54,51.48 47.69,51.63 47.69,51.77 47.45,52.01 47.45,52.15 48.36,53.06 55.4,53.06 55.99,53.65 U52.AH21 ; TP1MC7.1 55.69,25.06 U67.H3
  L3-SIGNAL w0.114: TP1MC7.1 55.78,24.97 54.81,24.97 54.74,25.05 51.69,25.05 50.98,24.34 50.72,24.34 50.55,24.51 48.44,24.51 48.03,24.11 47.6,24.11 47.09,24.62 45.62,24.62 45.34,24.89 44.37,24.89 44.15,25.12 43.81,25.12 43.59,24.89 TP1MB7.1 42.57,24.89 42.47,25 41.91,25 41.73,24.82 39.27,24.82 38.7,25.38 37.37,25.38 36.89,24.91 35.64,24.91 35.24,24.51 34.92,24.51 34.64,24.79 34.19,24.79 33.96,24.56 33.63,24.56 33.45,24.74 33.15,24.74 32.89,25 32.59,25 32.33,24.74 32.05,24.74 31.93,24.87 31.6,24.87 31.45,24.72 31.06,24.72 30.89,24.89 TP1MA7.1 29.91,24.89 29.84,24.97 28.4,24.97 28.14,24.72 26.92,24.72 26.42,25.22 25.93,25.22 25.35,25.81 25.35,26.04 25.25,26.14 24.94,26.14 24.84,26.24 24.84,26.44 24.94,26.55 25.25,26.55 25.37,26.67 25.37,27.28 25.25,27.41 24.82,27.41 24.33,27.89 24.08,27.89 23.9,27.71 v2(23.9,27.26)
  BOTTOM w0.127: TP1MC7.1 56.22,24.91 57.82,24.91 58.22,25.3 58.55,25.3 59.46,26.22 62.11,26.22 62.22,26.11 62.55,26.11 62.56,26.11 62.64,26.11 63.02,26.5 RN13.2
H_DDR2_A0: length 77.2
  TOP w0.102: v1(66.18,49.95) U52.R25
  TOP w0.127: U68.K3 80.16,23.46 80.3,23.32 TP2MA15.1 ; TP2MB15.1 94.65,23.32 94.51,23.46 U69.K3
  L3-SIGNAL w0.114: v2(65.18,35.89) 64.77,36.3 64.77,36.83 65.18,37.24 65.18,37.51 65.3,37.63 65.68,37.63 65.81,37.76 65.81,38 65.71,38.1 64.71,38.1 64.59,38.22 64.59,38.39 64.71,38.51 65.71,38.51 65.81,38.61 65.81,38.81 65.71,38.91 64.72,38.91 64.6,39.03 64.6,39.2 64.72,39.32 65.71,39.32 65.81,39.42 65.81,39.62 65.71,39.73 64.74,39.73 64.62,39.84 64.62,40.01 64.74,40.13 65.71,40.13 65.81,40.23 65.81,48.41 66.6,49.2 66.6,49.53 v1(66.18,49.95)
  L6-SIGNAL w0.102: v2(65.18,35.89) 70.18,30.89 70.18,30.18 74.24,26.11 75.31,26.11 77.09,24.34 77.57,24.34 77.77,24.54 78.69,24.54 80.04,23.19 80.54,23.19 80.67,23.32 TP2MA15.1 81.69,23.32 81.84,23.17 84.51,23.17 84.79,23.45 86.77,23.45 87.02,23.19 90.17,23.19 90.69,22.68 93.14,22.68 93.79,23.32 TP2MB15.1 96.04,23.32 96.16,23.19 98.7,23.19 98.96,23.45 99.8,23.45 100.61,22.63 102.13,22.63 102.72,22.05 v1(103.66,22.05)
  BOTTOM w0.127: U115.K3 96.94,23.46 96.65,23.17 96.24,23.17 96.09,23.32 TP2MB15.1 ; RN14.1 104.87,22.5 104.43,22.05 v1(103.66,22.05) ; TP2MA15.1 81.74,23.32 81.89,23.17 82.3,23.17 82.59,23.46 U116.K3
H_DDR2_A1: length 80.2
  TOP w0.102: v1(66.15,49.34) U52.R26
  TOP w0.127: TP2MA19.1 81.94,22.13 82.07,22.25 82.34,22.25 82.74,22.66 U68.L7 ; U69.L7 97.09,22.66 96.69,22.25 96.42,22.25 96.29,22.13 TP2MB19.1
  L6-SIGNAL w0.102: v1(103.02,21.14) 100.45,21.14 99.75,21.84 97.43,21.84 97.33,21.74 TP2MB19.1 95.91,21.92 95.4,21.92 95.28,21.8 94.82,21.8 94.46,22.15 94.11,22.15 93.75,21.8 92.48,21.8 92.4,21.88 91.8,21.88 91.29,21.36 86.87,21.36 86.74,21.49 86.38,21.49 86.01,21.86 84.45,21.86 84.1,21.52 82.17,21.52 TP2MA19.1 81.53,22.15 81.13,22.15 80.85,21.87 79.58,21.87 78.89,22.56 76.68,22.56 76.53,22.71 76.53,23.14 74.93,24.74 74.08,24.74 73.97,24.64 72.92,24.64 72.59,24.97 71.89,24.97 71.79,25.07 71.79,25.74 71.67,25.86 71.5,25.86 71.38,25.74 71.38,25.07 71.28,24.97 71.08,24.97 70.98,25.07 70.98,25.74 70.86,25.86 70.69,25.86 70.57,25.74 70.57,25.07 70.47,24.97 70.27,24.97 70.16,25.07 70.16,25.83 70.04,25.95 69.88,25.95 69.76,25.83 69.76,25.07 69.66,24.97 v2(68.73,24.97)
  BOTTOM w0.127: RN16.4 104.87,20.71 104.44,21.14 v1(103.02,21.14) ; U115.L7 94.51,22.33 94.51,22.18 94.87,21.82 95.23,21.82 95.36,21.95 96.09,21.95 TP2MB19.1 ; v2(68.73,24.97) 68.73,33.73 67.69,34.78 67.69,36.43 66.37,37.75 66.37,39.65 65.48,40.54 65.48,44.45 65.79,44.76 65.79,47.37 65.86,47.45 65.86,48.74 66.15,49.03 v1(66.15,49.34) ; U116.L7 80.16,22.33 80.16,22.18 80.52,21.82 80.88,21.82 81.01,21.95 81.74,21.95 TP2MA19.1
H_DDR2_A2: length 89.1
  TOP w0.127: U69.L3 94.56,22.66 94.67,22.76 95.17,22.76 95.68,22.25 TP2MB20.1 ; U68.L3 80.21,22.66 80.31,22.76 80.82,22.76 81.33,22.25 TP2MA20.1 ; U52.R28 66.73,46.95 66.55,46.76 66.55,40.36 66.95,39.96 68.35,39.96 71.07,37.24 71.07,32.46 71.4,32.13 71.4,31.1 71.3,31 70.41,31 70.31,30.9 70.31,30.69 70.41,30.59 71.3,30.59 71.4,30.49 71.4,30.29 71.3,30.18 70.41,30.18 70.31,30.08 70.31,29.88 70.41,29.78 71.3,29.78 71.4,29.68 71.4,29.47 71.3,29.37 70.41,29.37 70.31,29.27 70.31,29.07 70.41,28.96 71.3,28.96 71.4,28.86 71.4,28.66 71.3,28.56 70.41,28.56 70.31,28.46 70.31,28.25 70.41,28.15 71.3,28.15 71.4,28.05 71.4,27.85 71.3,27.75 70.41,27.75 70.31,27.64 70.31,27.44 70.41,27.34 71.3,27.34 71.4,27.24 71.4,27.03 71.3,26.93 70.41,26.93 70.31,26.83 70.31,26.63 70.41,26.53 71.3,26.53 71.4,26.42 71.4,26.22 71.3,26.12 70.31,26.12 70.17,25.98 70.17,25.24 70.69,24.72 70.69,23.57 71.42,22.84 71.42,21.77 71.65,21.54 v2(72.29,21.54) ; RN5.3 v1(103.66,23.07)
  L3-SIGNAL w0.102: 103.66,22.6 103.15,22.09
  L3-SIGNAL w0.114: v1(103.66,23.07) 103.66,22.6 ; 103.15,22.09 102.14,21.07 96.15,21.07 TP2MB20.1 95.28,21.69 93.45,21.69 93.27,21.87 88.27,21.87 87.8,22.34 86.36,22.34 85.88,21.86 84.62,21.86 84.12,21.36 81.52,21.36 TP2MA20.1 81.11,21.77 78.29,21.77 78.13,21.92 77.5,21.92 77.09,21.52 75.56,21.52 75.43,21.38 75.09,21.38 74.96,21.52 72.31,21.52 v2(72.29,21.54)
  BOTTOM w0.102: TP2MA20.1 81.58,21.29 82.06,21.29 82.65,21.88 82.65,22.28 U116.L3 ; TP2MB20.1 95.94,21.29 96.41,21.29 97,21.88 97,22.28 U115.L3
H_DDR2_A3: length 83.3
  TOP w0.127: U69.K2 93.78,23.85 94.59,23.85 94.73,23.71 95.58,23.71 95.72,23.57 96.34,23.57 TP2MB14.1 ; v2(70.89,31.83) 70.56,32.16 70.56,37.24 68.22,39.58 66.68,39.58 66.19,40.06 66.19,47.32 66.32,47.45 66.32,48.44 U52.R27 ; TP2MA14.1 81.99,23.57 81.37,23.57 81.23,23.71 80.4,23.71 80.26,23.85 79.43,23.85 U68.K2 ; RN5.1 v1(103.66,24.14)
  L3-SIGNAL w0.102: 103.49,24.14 102.84,24.14
  L3-SIGNAL w0.114: TP2MA14.1 83.48,23.65 84.1,24.26 84.99,24.26 85.54,24.82 91.64,24.82 92.2,24.26 93.24,24.26 93.8,23.71 95.78,23.71 95.83,23.65 TP2MB14.1 96.98,23.65 97.16,23.47 99.87,23.47 100.35,23.95 102.65,23.95 102.84,24.14 ; v1(103.66,24.14) 103.49,24.14
  L6-SIGNAL w0.102: TP2MA14.1 81.33,23.65 81.28,23.7 80.77,23.7 80.7,23.62 80.42,23.62 79.71,24.34 79.71,25.53 79.58,25.66 79.32,25.66 79.2,25.53 79.2,25.17 79.07,25.05 78.31,25.05 78.18,25.17 78.18,25.43 78.05,25.55 77.8,25.55 77.67,25.43 77.67,25.16 77.55,25.03 77.26,25.03 77.15,25.14 77.15,25.45 77.05,25.55 76.69,25.55 75.63,26.62 75.21,26.62 74.78,27.05 74.64,27.05 74.36,26.77 74.22,26.77 74.08,26.92 74.08,27.06 74.35,27.34 74.35,27.48 74.21,27.62 74.06,27.62 73.79,27.35 73.65,27.35 73.5,27.49 73.5,27.64 73.78,27.91 73.78,28.05 73.63,28.2 73.49,28.2 73.21,27.92 73.07,27.92 72.93,28.07 72.93,28.21 73.2,28.49 73.2,28.63 73.06,28.77 72.91,28.77 72.64,28.5 72.5,28.5 72.35,28.64 72.35,28.79 73.16,29.59 73.16,29.76 73.04,29.88 72.87,29.88 72.06,29.07 71.92,29.07 71.78,29.22 71.78,29.36 72.37,29.95 72.37,30.12 72.25,30.24 72.08,30.24 71.49,29.65 71.35,29.65 71.2,29.79 71.2,29.94 72.05,30.78 72.05,30.96 71.91,31.1 71.74,31.1 71.1,30.46 70.92,30.46 70.78,30.6 70.78,30.78 71.24,31.24 71.24,31.48 v2(70.89,31.83)
  BOTTOM w0.127: TP2MB14.1 96.7,23.85 97.79,23.85 U115.K2 ; U116.K2 83.44,23.85 82.35,23.85 TP2MA14.1
H_DDR2_A4: length 89.5
  TOP w0.127: RN5.4 v1(104.3,22.5) ; TP2MB17.1 96.62,22.89 96.98,22.89 97.13,23.04 97.8,23.04 U69.L8 ; U52.P23 67.13,51.65 67.13,46.38 66.9,46.15 66.9,40.74 67.31,40.34 68.48,40.34 72.03,36.78 72.03,36.53 71.93,36.43 71.55,36.43 71.45,36.32 71.45,36.12 71.55,36.02 71.93,36.02 72.03,35.92 72.03,35.71 71.93,35.61 71.55,35.61 71.45,35.51 71.45,35.31 71.55,35.21 71.93,35.21 72.03,35.1 72.03,34.9 71.93,34.8 71.55,34.8 71.45,34.7 71.45,34.49 71.55,34.39 71.93,34.39 72.03,34.29 72.03,34.09 71.93,33.99 71.55,33.99 71.45,33.89 71.45,33.68 71.55,33.58 71.93,33.58 72.03,33.48 72.03,33.28 71.93,33.17 71.55,33.17 71.45,33.07 71.45,32.87 71.55,32.77 71.93,32.77 72.03,32.67 72.03,24.54 71.91,24.41 71.7,24.41 71.58,24.54 71.58,25.5 71.45,25.63 71.07,25.63 70.94,25.5 70.94,25.17 71.15,24.97 71.15,23.95 71.27,23.83 v2(72.29,23.83) ; TP2MA17.1 82.27,22.89 82.63,22.89 82.78,23.04 83.45,23.04 U68.L8
  L3-SIGNAL w0.114: TP2MA17.1 81.79,22.41 81.2,22.41 80.81,22.8 79.07,22.8 78.93,22.66 77.09,22.66 76.97,22.78 76.97,23.18 76.85,23.29 76.68,23.29 76.56,23.18 76.56,22.78 76.46,22.68 75.85,22.68 75.46,23.07 72.42,23.07 72.29,23.19 v2(72.29,23.83)
  L6-SIGNAL w0.102: v1(104.3,22.5) 104.3,21.85 104.06,21.62 100.71,21.62 99.65,22.68 96.43,22.68 TP2MB17.1 96.15,22.42 95.42,22.42 95.18,22.66 93.85,22.66 93.47,22.28 90.55,22.28 89.97,22.86 87.4,22.86 86.89,22.35 86.4,22.35 86.09,22.66 86.09,22.76 85.99,22.86 85.79,22.86 85.68,22.76 85.68,22.66 85.58,22.56 85.34,22.56 85.24,22.66 84.81,22.66 84.58,22.43 82.32,22.43 TP2MA17.1
  BOTTOM w0.127: TP2MB17.1 96.14,22.41 95.48,22.41 95.2,22.68 94.79,22.68 94.41,23.07 93.79,23.07 U115.L8 ; U116.L8 79.44,23.07 80.06,23.07 80.44,22.68 80.85,22.68 81.13,22.41 81.79,22.41 TP2MA17.1
H_DDR2_A5: length 86.7
  TOP w0.102: U52.P22 v1(67.94,52.4)
  TOP w0.127: U69.L2 93.76,22.28 TP2MB18.1 ; TP2MA18.1 79.41,22.28 U68.L2 ; RN5.2 v1(104.3,23.57)
  L3-SIGNAL w0.114: v1(104.3,23.57) 103.57,23.57 102.97,22.96 102.74,22.96 101.63,21.85 96.74,21.85 96.31,22.28 TP2MB18.1 90.32,22.28 89.38,23.22 85.75,23.22 85.2,22.67 84.56,22.67 84.08,22.19 80.93,22.19 TP2MA18.1 75.36,22.28 74.96,22.68 73.81,22.68 73.71,22.58 v2(70.89,22.58)
  BOTTOM w0.102: 67.18,48.54 67.18,49.89 67.32,50.03
  BOTTOM w0.127: U115.L2 97.8,23.04 97.13,23.04 96.98,22.89 96.98,22.66 96.5,22.18 95.12,22.18 TP2MB18.1 ; v1(67.94,52.4) 67.32,51.78 67.32,50.03 ; U116.L2 83.45,23.04 82.78,23.04 82.63,22.89 82.63,22.66 82.15,22.18 80.77,22.18 TP2MA18.1 ; 67.18,48.54 67.09,48.45 67.09,46.76 66.9,46.57 66.9,42.52 68.1,41.33 68.1,39.07 71.32,35.84 71.32,28.51 71.22,28.41 70.92,28.41 70.82,28.3 70.82,28.1 70.92,28 71.22,28 71.32,27.9 71.32,27.69 71.22,27.59 70.92,27.59 70.82,27.49 70.82,27.29 70.92,27.19 71.22,27.19 71.32,27.08 71.32,26.88 71.22,26.78 70.92,26.78 70.82,26.68 70.82,26.47 70.92,26.37 71.22,26.37 71.32,26.27 71.32,26.07 71.22,25.97 70.92,25.97 70.82,25.87 70.82,25.66 70.92,25.56 71.22,25.56 71.32,25.46 71.32,25.26 71.22,25.15 70.92,25.15 70.82,25.05 70.82,24.85 70.92,24.75 71.22,24.75 71.32,24.65 71.32,24.44 71.22,24.34 70.92,24.34 70.82,24.24 70.82,24.04 70.92,23.93 71.22,23.93 71.32,23.83 71.32,23.57 71.2,23.45 70.18,23.45 70.05,23.32 70.05,23.07 70.18,22.94 70.54,22.94 v2(70.89,22.58)
H_DDR2_A6: length 88.4
  TOP w0.102: U52.P25 v1(68.04,49.82)
  TOP w0.127: U69.M8 97.82,22.23 97.08,22.23 96.7,21.85 96.7,21.58 96.41,21.29 96.06,21.29 95.5,20.73 TP2MB24.1 ; TP2MA24.1 81.15,20.73 81.71,21.29 82.06,21.29 82.35,21.58 82.35,21.85 82.73,22.23 83.46,22.23 U68.M8 ; RN7.3 v1(103.66,19.64)
  L3-SIGNAL w0.114: v2(73.18,20.53) 73.94,20.53 74,20.58 76.51,20.58 77.23,19.87 78.82,19.87 79.65,20.7 80.24,20.7 80.44,20.5 81,20.5 TP2MA24.1
  L6-SIGNAL w0.102: v1(103.66,19.64) 101.72,19.64 101.19,20.17 98.91,20.17 98.84,20.23 97.65,20.23 97.41,19.99 95.86,19.99 TP2MB24.1 93.73,20.35 93.22,19.84 92.05,19.84 91.49,19.28 87.91,19.28 86.96,20.23 83.08,20.23 82.84,19.99 81.51,19.99 TP2MA24.1
  BOTTOM w0.102: 67.79,48.76 67.61,48.94 67.61,49.52 67.73,49.64 v1(68.04,49.82)
  BOTTOM w0.127: TP2MB24.1 95.05,20.35 94.54,20.86 94.54,21.36 94.44,21.47 93.78,21.47 U115.M8 ; v2(73.18,20.53) 72.85,20.86 72.85,22.06 72.75,22.16 72.44,22.16 72.34,22.26 72.34,22.47 72.44,22.57 72.75,22.57 72.85,22.67 72.85,24.47 72.75,24.57 72.44,24.57 72.34,24.67 72.34,24.87 72.44,24.97 72.75,24.97 72.85,25.07 72.85,25.28 72.75,25.38 72.44,25.38 72.34,25.48 72.34,25.68 72.44,25.79 72.75,25.79 72.85,25.89 72.85,26.09 72.75,26.19 72.44,26.19 72.34,26.29 72.34,26.5 72.44,26.6 72.75,26.6 72.85,26.7 72.85,26.9 72.75,27.01 72.44,27.01 72.34,27.11 72.34,27.31 72.44,27.41 72.75,27.41 72.85,27.51 72.85,27.72 72.75,27.82 72.44,27.82 72.34,27.92 72.34,28.12 72.44,28.22 72.75,28.22 72.85,28.33 72.85,28.53 72.75,28.63 72.44,28.63 72.34,28.73 72.34,28.94 72.44,29.04 72.75,29.04 72.85,29.14 72.85,29.34 72.75,29.44 72.44,29.44 72.34,29.55 72.34,29.75 72.44,29.85 72.75,29.85 72.85,29.95 72.85,30.15 72.75,30.26 72.44,30.26 72.34,30.36 72.34,30.56 72.44,30.66 72.75,30.66 72.85,30.76 72.85,30.97 72.75,31.07 72.44,31.07 72.34,31.17 72.34,36.22 68.86,39.7 68.86,41.66 68.45,42.06 68.45,45.65 67.79,46.31 67.79,48.76 ; U116.M8 79.43,21.47 80.09,21.47 80.19,21.36 80.19,20.86 80.7,20.35 TP2MA24.1
H_DDR2_A7: length 87.9
  TOP w0.102: U52.N20 v1(68.73,54)
  TOP w0.127: TP2MA23.1 82.22,20.37 82.04,20.2 81.58,20.2 81.32,19.94 80.98,19.94 80.31,20.6 80.31,21.19 80.04,21.47 79.43,21.47 U68.M2 ; U69.M2 93.78,21.47 94.39,21.47 94.67,21.19 94.67,20.6 95.33,19.94 95.67,19.94 95.93,20.2 96.39,20.2 96.57,20.37 TP2MB23.1
  L3-SIGNAL w0.114: v2(72.29,20.53) 73.04,19.78 73.55,19.78 73.99,20.22 75.37,20.22 76.23,19.37 78.91,19.37 79.71,20.17 80.64,20.17 81,19.81 81.46,19.81 81.76,20.12 82.37,20.12 TP2MA23.1 84.33,20.37 84.43,20.27 86.94,20.27 87.66,20.98 91.08,20.98 92.21,19.86 93.17,19.86 93.25,19.94 96.55,19.94 TP2MB23.1 98.53,20.37 98.85,20.05 100.3,20.05 100.39,20.15 102.25,20.15 102.26,20.14 v1(103.02,20.14)
  BOTTOM w0.102: 67.64,51.15 67.55,51.06 67.55,49.84 67.39,49.67 67.39,48.76 67.46,48.68
  BOTTOM w0.127: U116.M2 83.44,21.47 82.91,21.47 82.63,21.19 TP2MA23.1 ; v1(68.73,54) 69.09,53.65 69.09,53.01 68.88,52.81 68.58,52.81 68.34,52.57 68.34,52.24 68.35,52.23 68.35,51.47 68.14,51.26 67.75,51.26 67.64,51.15 ; TP2MB23.1 96.98,21.19 97.26,21.47 97.79,21.47 U115.M2 ; v2(72.29,20.53) 71.83,20.98 71.83,36.03 68.48,39.38 68.48,41.56 68.05,41.99 68.05,45.57 67.46,46.15 67.46,48.68 ; RN16.3 104.87,20.14 104.47,20.55 104.13,20.55 103.72,20.14 v1(103.02,20.14)
H_DDR2_A8: length 93
  TOP w0.127: U68.N8 83.31,20.54 83.31,19.13 83.03,18.85 80.7,18.85 TP2MA27.1 ; U69.N8 97.66,20.54 97.66,19.13 97.38,18.85 95.05,18.85 TP2MB27.1 ; v2(73.43,21.95) 72.92,21.95 72.8,22.08 72.8,22.43 72.92,22.56 73.74,22.56 74.16,22.98 72.59,22.98 72.47,23.1 72.47,23.27 72.59,23.4 72.97,23.4 73.1,23.52 73.1,24.34 72.97,24.46 72.59,24.46 72.47,24.59 72.47,24.82 72.57,24.92 73,24.92 73.1,25.02 73.1,25.22 73,25.33 72.57,25.33 72.47,25.43 72.47,25.63 72.57,25.73 72.98,25.73 73.1,25.85 73.1,26.02 72.98,26.14 72.57,26.14 72.47,26.24 72.47,27.35 72.57,27.45 72.75,27.45 72.85,27.55 72.85,27.75 72.75,27.85 72.57,27.85 72.47,27.96 72.47,28.16 72.57,28.26 72.75,28.26 72.85,28.36 72.85,28.57 72.75,28.67 72.57,28.67 72.47,28.77 72.47,28.97 72.57,29.07 72.75,29.07 72.85,29.18 72.85,29.38 72.75,29.48 72.57,29.48 72.47,29.58 72.47,29.79 72.57,29.89 72.75,29.89 72.85,29.99 72.85,30.19 72.75,30.29 72.57,30.29 72.47,30.39 72.47,30.6 72.57,30.7 72.75,30.7 72.85,30.8 72.85,31 72.75,31.11 72.57,31.11 72.47,31.21 72.47,31.41 72.57,31.51 72.75,31.51 72.85,31.61 72.85,31.82 72.75,31.92 72.57,31.92 72.47,32.02 72.47,32.22 72.57,32.33 72.75,32.33 72.85,32.43 72.85,32.63 72.75,32.73 72.57,32.73 72.47,32.83 72.47,33.04 72.57,33.14 72.75,33.14 72.85,33.24 72.85,33.44 72.75,33.54 72.57,33.54 72.47,33.65 72.47,33.85 72.57,33.95 72.75,33.95 72.85,34.05 72.85,34.26 72.75,34.36 72.57,34.36 72.47,34.46 72.47,34.66 72.57,34.76 72.75,34.76 72.85,34.87 72.85,35.07 72.75,35.17 72.57,35.17 72.47,35.27 72.47,35.47 72.57,35.58 72.75,35.58 72.85,35.68 72.85,35.88 72.75,35.98 72.57,35.98 72.47,36.08 72.47,36.86 68.61,40.72 68.28,40.72 68.1,40.9 68.1,44.15 67.97,44.27 67.44,44.27 67.31,44.4 67.31,44.66 67.44,44.78 67.89,44.78 68.02,44.91 68.02,47.42 67.92,47.53 67.92,48.47 U52.P27
  L3-SIGNAL w0.114: TP2MA27.1 80.85,18.69 92.3,18.69 92.46,18.84 94.23,18.84 TP2MB27.1 95.24,18.65 101.12,18.65 101.15,18.62 v1(103.66,18.62)
  L6-SIGNAL w0.102: TP2MA27.1 79.86,19.69 79.07,19.69 78.63,19.24 77.95,19.24 77.95,19.21 77.71,18.98 77.38,18.98 77.14,19.21 77.14,19.24 75.47,19.24 74.39,20.32 74.02,20.32 73.43,20.91 v2(73.43,21.95)
  BOTTOM w0.127: U115.N8 93.38,20.51 TP2MB27.1 ; TP2MA27.1 79.03,20.51 U116.N8 ; v1(103.66,18.62) 104.43,18.62 104.87,19.07 RN16.1
H_DDR2_A9: length 75.4
  TOP w0.127: U68.M3 80.18,21.86 TP2MA21.1 ; U69.M3 94.53,21.86 TP2MB21.1 ; U52.N27 68.69,48.5 68.69,41.65 74.12,36.22 74.12,35.26 74.22,35.16 74.65,35.16 74.75,35.06 74.75,34.86 74.65,34.75 74.22,34.75 74.12,34.65 74.12,34.45 74.22,34.35 74.65,34.35 74.75,34.25 74.75,34.04 74.65,33.94 74.22,33.94 74.12,33.84 74.12,33.64 74.22,33.53 74.65,33.53 74.75,33.43 74.75,33.23 74.65,33.13 74.22,33.13 74.12,33.03 74.12,32.82 74.22,32.72 74.65,32.72 74.75,32.62 74.75,31.63 74.12,30.99 74.12,28.4 74.47,28.04 74.47,25.38 74.18,25.09 74.05,25.09 73.99,25.15 73.74,25.15 73.51,24.92 73.51,24.31 73.81,24.01 v2(73.81,23.57) ; RN7.1 v1(103.66,20.71)
  L6-SIGNAL w0.102: v1(103.66,20.71) 103.33,20.71 103.16,20.55 102.33,20.55 102.03,20.25 101.88,20.25 101.6,20.53 100.06,20.53 99.55,21.04 95.73,21.04 TP2MB21.1 94.46,21.19 94.32,21.04 93.48,21.04 93.38,21.14 93.38,21.26 93.28,21.36 93.08,21.36 92.97,21.26 92.97,21.14 92.87,21.04 81.58,21.04 81.4,20.86 81.18,20.86 TP2MA21.1 80.62,21.41 80.11,21.41 79.91,21.21 79.04,21.21 78.92,21.34 78.92,21.87 78.79,22 77.34,22 77.24,21.9 77.24,21.64 77.14,21.54 76.93,21.54 76.83,21.64 76.83,21.9 76.73,22 76.4,22 75.55,22.85 75.55,23.35 75.32,23.57 v2(73.81,23.57)
  BOTTOM w0.102: TP2MB21.1 95.33,21.06 96.5,21.06 97.3,21.86 U115.M3 ; TP2MA21.1 80.98,21.06 82.15,21.06 82.95,21.86 U116.M3
H_DDR2_A10: length 79.2
  TOP w0.102: v1(68.77,51.65) U52.N23
  TOP w0.127: RN3.1 v1(103.66,27.57) ; U68.H7 82.74,25.35 82.12,25.35 82,25.47 82,25.82 TP2MA7.1 ; U69.H7 97.09,25.35 96.47,25.35 96.35,25.47 96.35,25.82 TP2MB7.1
  L3-SIGNAL w0.114: v2(67.18,35.31) 68.45,35.31 68.58,35.44 68.58,35.64 68.45,35.77 67.67,35.77 67.54,35.89 67.54,36.11 67.67,36.24 68.05,36.24 68.15,36.34 68.15,37.54 68.28,37.67 68.53,37.67 68.66,37.8 68.66,38.3 68.76,38.4 69.68,38.4 69.8,38.52 69.8,38.68 69.68,38.8 68.76,38.8 68.66,38.91 68.66,39.11 68.76,39.21 69.05,39.21 69.16,39.33 69.16,39.5 69.05,39.62 68.76,39.62 68.66,39.72 68.66,39.92 68.76,40.02 69.05,40.02 69.16,40.14 69.16,40.31 69.05,40.43 68.76,40.43 68.66,40.53 68.66,40.87 69.04,41.25 69.04,48.72 69.29,48.97 69.29,51.13 v1(68.77,51.65) ; v1(103.66,27.57) 101.51,27.57 100.58,26.65 100.58,26.22 100.33,25.96 TP2MB7.1 95.76,25.96 95.27,25.47 94.91,25.47 94.45,25.94 TP2MA7.1
  L6-SIGNAL w0.102: v2(67.18,35.31) 69.9,32.59 71.27,32.59 72.71,31.15 72.71,31.01 72.57,30.87 72.57,30.7 72.69,30.58 72.86,30.58 73,30.72 73.14,30.72 73.61,30.25 73.61,28.98 74.57,28.02 74.85,28.02 75.82,27.05 75.82,26.72 75.95,26.6 75.95,26.59 76.45,26.09 80.01,26.09 80.24,26.32 80.87,26.32 81.13,26.06 81.56,26.06 81.64,26.14 81.94,26.14 TP2MA7.1
  BOTTOM w0.127: U116.H7 80.21,25.44 80.21,26.04 80.47,26.29 80.95,26.29 81.2,26.04 82.04,26.04 TP2MA7.1 ; U115.H7 94.56,25.44 94.56,26.04 94.82,26.29 95.3,26.29 95.55,26.04 96.42,26.04 TP2MB7.1
H_DDR2_A11: length 82.2
  TOP w0.102: U52.P26 v1(67.99,49.26)
  TOP w0.127: U69.M7 97.14,21.86 96.95,21.67 96.95,21.39 96.49,20.93 96.37,20.93 TP2MB22.1 ; U68.M7 82.79,21.86 82.6,21.67 82.6,21.39 82.14,20.93 82.02,20.93 TP2MA22.1 ; RN7.2 v1(104.3,20.14)
  L3-SIGNAL w0.114: v1(104.3,20.14) 103.69,20.14 103.3,20.53 100.05,20.53 99.8,20.27 99.23,20.27 98.74,20.76 96.53,20.76 96.42,20.65 TP2MB22.1 95.94,20.81 95.93,20.8 94.93,20.8 94.65,21.07 91.69,21.07 91.47,21.29 87,21.29 86.75,21.05 82.5,21.05 82.1,20.65 TP2MA22.1 81.32,20.8 80.68,20.8 80.24,21.24 78.71,21.24 78.54,21.06 73.96,21.06 v2(73.94,21.03)
  BOTTOM w0.127: U116.M7 80.1,21.86 80.44,21.52 80.44,21.01 80.7,20.75 81.64,20.75 TP2MA22.1 ; TP2MB22.1 95.99,20.75 95.05,20.75 94.79,21.01 94.79,21.52 94.45,21.86 U115.M7 ; v1(67.99,49.26) 67.99,48.95 68.12,48.82 68.12,46.42 68.73,45.81 68.73,42.24 69.24,41.73 69.24,40.08 72.85,36.48 72.85,32.08 73.36,31.57 73.36,31.27 73.46,31.17 73.89,31.17 73.99,31.07 73.99,30.86 73.89,30.76 73.46,30.76 73.36,30.66 73.36,30.46 73.46,30.36 73.89,30.36 73.99,30.25 73.99,30.05 73.89,29.95 73.46,29.95 73.36,29.85 73.36,29.64 73.46,29.54 73.89,29.54 73.99,29.44 73.99,29.24 73.89,29.14 73.46,29.14 73.36,29.03 73.36,28.83 73.46,28.73 73.89,28.73 73.99,28.63 73.99,28.43 73.89,28.32 73.46,28.32 73.36,28.22 73.36,28.02 73.46,27.92 74.13,27.92 74.24,27.8 74.24,27.63 74.13,27.51 73.46,27.51 73.36,27.41 73.36,27.21 73.46,27.1 74.13,27.1 74.24,26.99 74.24,26.82 74.13,26.7 73.46,26.7 73.36,26.6 73.36,26.37 73.48,26.24 74.12,26.24 74.24,26.11 74.24,25.35 74.12,25.22 73.48,25.22 73.36,25.1 73.36,24.64 73.46,24.54 73.46,24.13 73.36,24.03 73.36,22.68 73.48,22.56 73.81,22.56 73.86,22.51 73.86,21.11 v2(73.94,21.03)
H_DDR2_A12: length 83.2
  TOP w0.127: U69.K7 96.94,23.46 96.65,23.17 96.14,23.17 TP2MB16.1 ; v2(73.61,25.73) 74.07,25.73 74.19,25.86 74.19,26.49 74.07,26.62 72.97,26.62 72.85,26.75 72.85,26.95 72.97,27.08 74.09,27.08 74.17,27.16 74.17,27.69 74.09,27.76 73.35,27.76 73.23,27.88 73.23,28.05 73.35,28.17 73.63,28.17 73.74,28.27 73.74,28.47 73.63,28.57 73.37,28.57 73.25,28.69 73.25,28.86 73.37,28.98 73.63,28.98 73.74,29.08 73.74,29.28 73.63,29.39 73.4,29.39 73.28,29.51 73.28,29.67 73.4,29.79 73.63,29.79 73.74,29.89 73.74,30.1 73.63,30.2 73.41,30.2 73.3,30.3 73.3,30.5 73.41,30.61 73.63,30.61 73.74,30.71 73.74,30.91 73.63,31.01 73.41,31.01 73.3,31.11 73.3,31.32 73.41,31.42 73.63,31.42 73.74,31.52 73.74,31.72 73.63,31.82 73.41,31.82 73.3,31.93 73.3,32.13 73.41,32.23 73.63,32.23 73.74,32.33 73.74,32.54 73.63,32.64 73.41,32.64 73.3,32.74 73.3,32.94 73.41,33.04 73.63,33.04 73.74,33.15 73.74,33.35 73.63,33.45 73.41,33.45 73.3,33.55 73.3,33.75 73.41,33.86 73.63,33.86 73.74,33.96 73.74,34.16 73.63,34.26 73.41,34.26 73.3,34.36 73.3,34.57 73.41,34.67 73.63,34.67 73.74,34.77 73.74,34.97 73.63,35.08 73.41,35.08 73.3,35.18 73.3,35.38 73.41,35.48 73.63,35.48 73.74,35.58 73.74,35.79 73.63,35.89 73.41,35.89 73.3,35.99 73.3,36.53 68.38,41.46 68.38,45.39 68.33,45.44 U52.N28 ; TP2MA16.1 81.79,23.17 82.3,23.17 82.59,23.46 U68.K7
  L3-SIGNAL w0.114: v1(103.02,23.57) 100.45,23.57 99.55,22.67 97.19,22.67 96.79,23.07 96.04,23.07 TP2MB16.1 93.9,22.81 93.26,23.46 91.48,23.46 90.7,24.24 88.36,24.24 87.57,23.45 84.71,23.45 84.43,23.17 81.79,23.17 TP2MA16.1
  L6-SIGNAL w0.102: TP2MA16.1 80.29,22.81 80.19,22.71 80.19,22.41 80.08,22.3 79.88,22.3 79.78,22.41 79.78,22.71 79.68,22.81 79.45,22.81 79.2,23.07 79.2,23.29 79.02,23.47 77.62,23.47 77.42,23.27 77.19,23.27 75.51,24.95 75.3,24.95 75.2,25.05 75.2,25.58 75.08,25.69 74.92,25.69 74.47,25.25 73.98,25.25 73.68,24.95 73.27,24.95 72.33,25.89 72.33,26.52 72.45,26.65 72.97,26.65 73.1,26.52 73.1,25.86 73.23,25.73 v2(73.61,25.73)
  BOTTOM w0.127: U115.K7 94.51,23.46 95.06,22.91 95.34,22.91 95.45,22.81 TP2MB16.1 ; U116.K7 80.16,23.46 80.71,22.91 80.99,22.91 81.1,22.81 TP2MA16.1 ; RN14.3 104.87,23.57 104.47,23.98 104.13,23.98 103.72,23.57 v1(103.02,23.57)
H_DDR2_A13: length 83.7
  TOP w0.102: v1(66.3,53.25) U52.T22
  TOP w0.127: TP2MA26.1 82.17,19.92 81.66,19.92 81.41,19.66 80.8,19.66 79.83,20.63 U68.N3 ; U69.N3 94.18,20.63 95.15,19.66 95.76,19.66 96.01,19.92 96.52,19.92 TP2MB26.1
  L6-SIGNAL w0.102: v1(103.02,19.07) 100.86,19.07 100.42,19.51 99.59,19.51 99.47,19.38 97.94,19.38 97.82,19.51 TP2MB26.1 96.52,19.1 95.43,19.1 94.84,19.69 93.57,19.69 92.86,18.98 85.65,18.98 85.24,19.38 83.72,19.38 83.59,19.51 TP2MA26.1 82.07,19 81.31,19 80.31,19.99 77.04,19.99 76.46,20.58 75.34,20.58 74.32,21.59 74.19,21.59 73.86,21.92 73.86,22.3 73.63,22.53 72.62,22.53 72.04,23.11 71.9,23.11 71.66,22.87 71.52,22.87 71.38,23.01 71.38,23.16 71.61,23.4 71.61,23.54 71.45,23.7 70,23.7 69.75,23.95 v2(69.75,23.88)
  BOTTOM w0.102: 66.5,48.62 66.78,48.9 66.78,50.18 66.75,50.2 66.75,52.8 v1(66.3,53.25)
  BOTTOM w0.127: v2(69.75,23.88) 69.75,24.89 69.89,25.03 69.89,28.92 70.23,29.26 70.23,30.94 69.75,31.42 69.75,34.62 68.73,35.64 68.73,36.91 67.26,38.38 67.26,40.16 66.19,41.23 66.19,44.02 66.34,44.17 66.34,47.06 66.5,47.21 66.5,48.62 ; U116.N3 83.03,20.22 TP2MA26.1 ; v1(103.02,19.07) 103.72,19.07 104.3,19.64 RN16.2 ; TP2MB26.1 97.38,20.22 U115.N3
